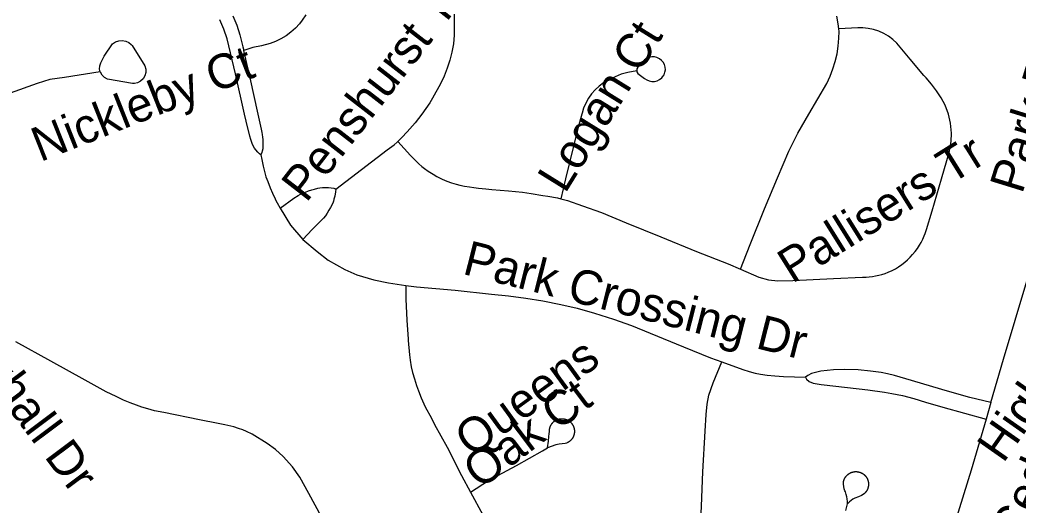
# Model space of a CAD drawing. Extents: x 1383679 to 1536984, y 460658 to 651027.
# Drawn here: x 1441302 to 1444051, y 495990 to 497325 of the extents above; entities that cross this region are included whole.
import ezdxf

# ---------------------------------------------------------------- set-up
doc = ezdxf.new("R2010")
doc.units = 0
doc.layers.add('Exist Road Non-System Type 51', color=7, linetype='Continuous')
doc.layers.add('Exist Road Non-System Type 51 Label', color=7, linetype='Continuous')

msp = doc.modelspace()

# ---------------------------------------------------------------- linework, layer by layer
at = {"layer": 'Exist Road Non-System Type 51'}
msp.add_line((1443976, 496272.3), (1443962.6, 496226.4), dxfattribs=at)
for points in [[(1443976, 496272.3), (1444010.6, 496391), (1444075, 496605.8), (1444091.2, 496671.9), (1444126.5, 496801.9), (1444159.9, 496915), (1444201.7, 497061.2), (1444203.1, 497066), (1444258.6, 497256.9), (1444298.8, 497399.9), (1444355.4, 497592.6), (1444400.6, 497747.6), (1444423.3, 497828.4), (1444445.6, 497913.6), (1444461.2, 497973.2), (1444493.5, 498085.3), (1444514.6, 498156.8)], [(1441888.4, 497336.8), (1441898.7, 497310.8), (1441907.5, 497284.3), (1441915.7, 497251.4), (1441918.1, 497241.2)], [(1442089.1, 497339.5), (1442079, 497324.4), (1442071.3, 497314.4), (1442060.2, 497302.3), (1442048, 497291.3), (1442034.8, 497281.6), (1442020.7, 497273.1), (1442005.9, 497266.1), (1441990.5, 497260.5), (1441966.9, 497254.1), (1441942.9, 497249.2), (1441940.1, 497248.7), (1441918.1, 497241.2)], [(1442497.6, 497341.2), (1442498, 497282.8), (1442495.5, 497259.7), (1442491.4, 497236.8), (1442485.7, 497214.3), (1442478.6, 497192.1), (1442470, 497170.5), (1442459.9, 497149.6), (1442438, 497109.7), (1442430.8, 497097.2), (1442408.6, 497066), (1442390.5, 497041.9), (1442368.6, 497017.3), (1442353.6, 497001.6), (1442342.5, 496990.3)], [(1443556.8, 497300.4), (1443555.2, 497314.5), (1443551.3, 497335.1)], [(1441965.1, 496953.3), (1441961.7, 496956.9), (1441956.9, 496961.5), (1441951.6, 496967.1), (1441947.9, 496971.9), (1441943.9, 496978.7), (1441941.4, 496985.1), (1441937.7, 496996.3), (1441935.3, 497005.4), (1441924.8, 497046.7), (1441920.4, 497066), (1441895.8, 497176.5), (1441872.1, 497273.5), (1441863.1, 497299.5), (1441852.6, 497325)], [(1443286.6, 496638.5), (1443336.6, 496617.3), (1443363.7, 496609.8), (1443388.9, 496607.2), (1443430.5, 496607.9), (1443542.3, 496613.3), (1443622.5, 496616.9), (1443624, 496617), (1443632.3, 496617.2), (1443640.2, 496617.7), (1443650.1, 496618.9), (1443658.2, 496620.3), (1443667.5, 496622.3), (1443675.3, 496624.4), (1443684.3, 496627.3), (1443693.1, 496630.7), (1443703.7, 496635.6), (1443712.8, 496640.3), (1443721.1, 496645.3), (1443730.2, 496651.5), (1443738.6, 496657.9), (1443746.4, 496664.7), (1443753.8, 496671.8), (1443760.4, 496678.9), (1443767.6, 496687.7), (1443773.5, 496695.9), (1443779.5, 496705.2), (1443783.8, 496712.8), (1443788.1, 496721.3), (1443792, 496730.4), (1443794.6, 496737.2), (1443798.1, 496748), (1443814.1, 496799.6), (1443840.3, 496888.1), (1443860.7, 496959.7), (1443866.5, 496990), (1443867.2, 497013.3), (1443864.8, 497040.8), (1443859, 497066), (1443850.1, 497090.2), (1443838.9, 497110.5), (1443826.3, 497130), (1443812.4, 497148.5), (1443797.3, 497166.1), (1443791.3, 497172.4), (1443754, 497216.9), (1443716.8, 497261.4), (1443705.7, 497271.5), (1443693.7, 497280.3), (1443680.8, 497287.8), (1443667.1, 497293.9), (1443652.9, 497298.6), (1443638.3, 497301.7), (1443623.4, 497303.3), (1443609, 497303.3), (1443556.8, 497300.4)], [(1443286.6, 496638.5), (1443294.2, 496660.4), (1443313.2, 496706.7), (1443352.6, 496805.1), (1443388.1, 496890.6), (1443419.3, 496963.6), (1443444.5, 497013.1), (1443474.5, 497066), (1443523.8, 497150.5), (1443533.1, 497170), (1443541, 497190.2), (1443547.4, 497210.8), (1443552.3, 497231.9), (1443555.6, 497253.2), (1443557.3, 497274.8), (1443557.6, 497293.6), (1443556.8, 497300.4)], [(1441523, 497182), (1441521.1, 497189.9), (1441521.7, 497199.1), (1441524.6, 497207.2), (1441525.7, 497209.1), (1441534.1, 497225), (1441556.4, 497258.9), (1441565.1, 497264.8), (1441574.1, 497268), (1441583.6, 497268.8), (1441593, 497267.1), (1441601.7, 497263.2), (1441608.5, 497257.6), (1441610.9, 497255), (1441645.5, 497198.4), (1441648.1, 497189.5), (1441648.2, 497180.1), (1441645.7, 497171), (1441640.9, 497162.9), (1441634.2, 497156.5), (1441625.9, 497152), (1441617.1, 497150.1), (1441611.4, 497150.1), (1441542.9, 497162.1), (1441534.6, 497166.4), (1441527.9, 497172.8), (1441523.3, 497180.9), (1441523, 497182)], [(1441965.1, 496953.3), (1441968.5, 496960), (1441970.1, 496965), (1441971.4, 496971.4), (1441971.8, 496977), (1441971.9, 496983.6), (1441971.8, 496990.4), (1441971.4, 496996.4), (1441971, 497002.8), (1441969.9, 497009.8), (1441968.8, 497014.9), (1441966.8, 497024.3), (1441957.9, 497066), (1441936, 497165.9), (1441918.1, 497241.2)], [(1443000.5, 497185.3), (1443001.2, 497182), (1443003.5, 497178.1), (1443007, 497175.3), (1443007.1, 497175.3), (1443021.9, 497164.1), (1443028.1, 497159.9), (1443035, 497157.1), (1443042.3, 497155.8), (1443049.7, 497156), (1443056.9, 497157.9), (1443063.6, 497161.2), (1443069.4, 497165.8), (1443071.6, 497168.2), (1443075.6, 497174.2), (1443078.2, 497180.9), (1443079.3, 497188), (1443078.9, 497195.2), (1443076.8, 497202.1), (1443073.4, 497208.4), (1443068.6, 497213.8), (1443068.6, 497213.8), (1443062.8, 497218.3), (1443056.1, 497221.5), (1443049, 497223.3), (1443041.6, 497223.5), (1443034.3, 497222.1), (1443027.5, 497219.2), (1443021.5, 497215), (1443019.9, 497213.4), (1443006.5, 497197.6), (1443003.2, 497194.7), (1443001, 497190.8), (1443000.3, 497186.3), (1443000.5, 497185.3)], [(1441523, 497182), (1441424.4, 497166.6), (1441383.8, 497160.8), (1441348.9, 497150.2), (1441275.1, 497123.9)], [(1443000.5, 497185.3), (1442975.5, 497180.4), (1442957.9, 497175.4), (1442940.9, 497168.9), (1442924.5, 497160.9), (1442908.8, 497151.5), (1442897.1, 497143.2), (1442886.1, 497132.9), (1442876.2, 497121.6), (1442867.5, 497109.3), (1442860.2, 497096.2), (1442854.3, 497082.4), (1442849.9, 497068), (1442849.4, 497066), (1442839.5, 497029.5), (1442804.2, 496888), (1442791.8, 496833)], [(1442171.3, 496859.6), (1442313.1, 496967.5), (1442332.1, 496981.4), (1442340.6, 496988.4), (1442342.5, 496990.3)], [(1442342.5, 496990.3), (1442377, 496951.8), (1442385.3, 496943.9), (1442392.9, 496936), (1442400.1, 496929.3), (1442408.6, 496921.5), (1442415.5, 496915.9), (1442426.1, 496908.8), (1442439.5, 496900.2), (1442449.9, 496894.1), (1442464.9, 496887.1), (1442477.5, 496881.6), (1442490.4, 496876.7), (1442502.7, 496872.8), (1442513.4, 496870.2), (1442525.9, 496867.5), (1442540.3, 496865.2), (1442551.7, 496863.8), (1442565.1, 496862), (1442585.2, 496860), (1442601.7, 496858.4), (1442647.7, 496854.3), (1442686.1, 496850.5), (1442710, 496847.1), (1442741.5, 496842.2), (1442755.7, 496839.5), (1442781.8, 496835.7), (1442791.8, 496833)], [(1441965.1, 496953.3), (1441967.5, 496940.6), (1441971.2, 496922.3), (1441975, 496907.5), (1441979.3, 496893.6), (1441984, 496880), (1441990.8, 496862.8), (1441997, 496848), (1442004.4, 496832.4), (1442004.9, 496831.3), (1442009.8, 496821.6), (1442018.2, 496806.6)], [(1442018.2, 496806.6), (1442056.1, 496834.3), (1442067.8, 496841.8), (1442074.3, 496845.3), (1442079.9, 496848.1), (1442087.9, 496851.4), (1442096.3, 496854.5), (1442105.2, 496857.3), (1442113.2, 496859.6), (1442122.4, 496861.7), (1442127.8, 496862.6), (1442135.3, 496863.4), (1442143.3, 496863.5), (1442151.6, 496863.4), (1442159.3, 496863), (1442166, 496862.1), (1442169, 496860.8), (1442171.3, 496859.6)], [(1442171.3, 496859.6), (1442170.6, 496851.6), (1442168.6, 496839.9), (1442166.6, 496831.3), (1442164.9, 496825.4), (1442164.9, 496825.4), (1442164.9, 496825.3), (1442164.9, 496825.3), (1442164.9, 496825.2), (1442164.8, 496825.2), (1442164.8, 496825.1), (1442164.8, 496825.1), (1442164.8, 496825), (1442164.8, 496825), (1442164.8, 496824.9), (1442164.8, 496824.9), (1442164.7, 496824.8), (1442164.7, 496824.8), (1442164.7, 496824.7), (1442164.7, 496824.7), (1442164.7, 496824.6), (1442164.7, 496824.6), (1442164.7, 496824.5), (1442164.6, 496824.5), (1442164.6, 496824.4), (1442164.6, 496824.4), (1442164.6, 496824.3), (1442164.6, 496824.3), (1442164.6, 496824.2), (1442164.6, 496824.2), (1442164.5, 496824.1), (1442164.5, 496824.1), (1442164.5, 496824), (1442164.5, 496824), (1442164.5, 496823.9), (1442164.5, 496823.9), (1442164.4, 496823.8), (1442164.4, 496823.8), (1442164.4, 496823.7), (1442164.4, 496823.7), (1442164.4, 496823.6), (1442164.4, 496823.6), (1442164.3, 496823.5), (1442164.3, 496823.5), (1442164.3, 496823.4), (1442164.3, 496823.4), (1442161.5, 496817), (1442157.1, 496808.7), (1442152.9, 496801.5), (1442147.9, 496793.5), (1442142.9, 496786.2), (1442137.7, 496779.3), (1442133.5, 496774.4), (1442123.5, 496764.7), (1442118.2, 496759.7), (1442107, 496748.2), (1442080.9, 496720.9)], [(1442018.2, 496806.6), (1442047.3, 496760.5), (1442080.9, 496720.9)], [(1442791.8, 496833), (1442810.2, 496827.9), (1442851.5, 496813.1), (1442903, 496794.8), (1442971.5, 496766.1), (1443066.8, 496728.4), (1443165.4, 496688), (1443252, 496653.3), (1443286.6, 496638.5)], [(1442080.9, 496720.9), (1442120.5, 496687.5), (1442150.5, 496664.1), (1442196.8, 496637.8), (1442229.9, 496623.8), (1442276.8, 496610), (1442316.5, 496601), (1442364.5, 496594.3)], [(1442364.5, 496594.3), (1442364.3, 496556.6), (1442367.5, 496498.9), (1442371.2, 496446.2), (1442371.4, 496442.9), (1442374.2, 496403.5), (1442376.5, 496388.1), (1442379.6, 496369.8), (1442383, 496354.3), (1442388, 496336.9), (1442393.8, 496318.6), (1442399.2, 496303.7), (1442406.7, 496285.1), (1442418.1, 496260.2), (1442434.8, 496228.3), (1442443.5, 496211.7), (1442478, 496148.8), (1442518.2, 496070.5), (1442542.7, 496025.3)], [(1442364.5, 496594.3), (1442394.2, 496590.2), (1442500.5, 496580.8), (1442600.3, 496570.4), (1442647.4, 496565.5), (1442695.2, 496558.8), (1442741.5, 496551.5), (1442791.2, 496541.4), (1442836.2, 496531.2), (1442884, 496517.4), (1442936.3, 496501.5), (1442986.3, 496484.1), (1443037.5, 496463.2), (1443129.3, 496425.3), (1443203.3, 496395.2), (1443234.6, 496384)], [(1442132.2, 495957), (1442097.7, 496021.6), (1442072.7, 496066.2), (1442052.3, 496094.6), (1442026.9, 496123), (1442005.8, 496142.2), (1441982.9, 496159.4), (1441941.4, 496184.4), (1441926, 496191.8), (1441915.2, 496196.5), (1441903.8, 496200.5), (1441891.2, 496204.6), (1441866.3, 496210.4), (1441847.6, 496214.5), (1441796, 496224.5), (1441698.2, 496243.9), (1441672.2, 496249.2), (1441654, 496254), (1441637.2, 496259.3), (1441622.5, 496264.1), (1441605.1, 496270.7), (1441586.5, 496278.7), (1441566.3, 496288.1), (1441538.8, 496301.4), (1441481.7, 496332.9), (1441386.9, 496385.9), (1441290.3, 496439.1)], [(1443095.4, 495761.7), (1443101.6, 495768), (1443111.5, 495779.3), (1443119.8, 495789.6), (1443128.6, 495802), (1443137.1, 495815.2), (1443148.1, 495834.6), (1443155, 495850.3), (1443161.6, 495868.4), (1443166.7, 495886.2), (1443171.6, 495907.9), (1443174.7, 495928.4), (1443176.9, 495948.2), (1443178.6, 495986.7), (1443182.9, 496081.4), (1443188.7, 496192.5), (1443191.5, 496238.4), (1443194.3, 496267), (1443199.3, 496292.4), (1443211.2, 496326.3), (1443234.6, 496384)], [(1443234.6, 496384), (1443293.1, 496362.9), (1443310, 496357), (1443327, 496353), (1443341.3, 496349.9), (1443359.6, 496346.7), (1443381.1, 496345.1), (1443405, 496343.3), (1443464.9, 496341.2)], [(1443976, 496272.3), (1443917.5, 496286), (1443856.4, 496303.4), (1443741.4, 496337.4), (1443710.1, 496346.4), (1443691.4, 496350.8), (1443674, 496354), (1443643.9, 496358.3), (1443609.9, 496361.8), (1443573.2, 496362.6), (1443542, 496361.6), (1443507.2, 496358.1), (1443482, 496351.9), (1443471.4, 496346), (1443464.9, 496341.2)], [(1443464.9, 496341.2), (1443467.7, 496335.7), (1443475.2, 496330), (1443486.7, 496325.4), (1443508.7, 496321.5), (1443581, 496313.3), (1443637.4, 496306.4), (1443683.3, 496300), (1443703.3, 496297), (1443732.8, 496291.1), (1443763.4, 496283), (1443795.9, 496273.1), (1443843.2, 496259.1), (1443962.6, 496226.4)], [(1442755, 496146.9), (1442757.9, 496165.2), (1442758.8, 496178), (1442759.5, 496186), (1442759.9, 496192.3), (1442760.6, 496198.2), (1442762.5, 496205.1), (1442765.2, 496211.6), (1442765.6, 496212.1), (1442765.9, 496212.6), (1442766.3, 496213.1), (1442766.6, 496213.6), (1442767, 496214), (1442767.4, 496214.5), (1442767.8, 496215), (1442768.2, 496215.4), (1442768.6, 496215.9), (1442769, 496216.3), (1442769.4, 496216.8), (1442769.8, 496217.2), (1442770.3, 496217.6), (1442770.7, 496218), (1442771.2, 496218.4), (1442771.6, 496218.8), (1442772.1, 496219.2), (1442772.6, 496219.6), (1442773, 496220), (1442773.5, 496220.3), (1442774, 496220.7), (1442774.5, 496221), (1442775, 496221.4), (1442775.5, 496221.7), (1442776, 496222), (1442776.5, 496222.3), (1442777.1, 496222.6), (1442777.6, 496222.9), (1442778.1, 496223.2), (1442778.6, 496223.5), (1442779.2, 496223.7), (1442779.7, 496224), (1442780.3, 496224.2), (1442780.8, 496224.5), (1442781.4, 496224.7), (1442782, 496224.9), (1442782.5, 496225.1), (1442783.1, 496225.3), (1442783.7, 496225.5), (1442784.3, 496225.7), (1442784.8, 496225.9), (1442785.4, 496226), (1442786, 496226.2), (1442786.6, 496226.3), (1442787.2, 496226.4), (1442787.8, 496226.6), (1442788.4, 496226.7), (1442789, 496226.8), (1442789.6, 496226.8), (1442790.2, 496226.9), (1442790.8, 496227), (1442791.4, 496227), (1442792, 496227.1), (1442792.6, 496227.1), (1442793.2, 496227.1), (1442793.8, 496227.2), (1442794.4, 496227.2), (1442795, 496227.1), (1442795.6, 496227.1), (1442796.2, 496227.1), (1442796.8, 496227.1), (1442797.4, 496227), (1442798, 496227), (1442798.6, 496226.9), (1442799.2, 496226.8), (1442799.8, 496226.7), (1442800.4, 496226.6), (1442801, 496226.5), (1442801.6, 496226.4), (1442802.2, 496226.2), (1442802.7, 496226.1), (1442803.3, 496225.9), (1442803.9, 496225.8), (1442804.5, 496225.6), (1442805.1, 496225.4), (1442805.6, 496225.2), (1442806.2, 496225), (1442806.8, 496224.8), (1442807.3, 496224.6), (1442807.9, 496224.4), (1442808.4, 496224.1), (1442809, 496223.9), (1442809.5, 496223.6), (1442810.1, 496223.3), (1442810.6, 496223), (1442811.1, 496222.8), (1442811.7, 496222.5), (1442812.2, 496222.2), (1442812.7, 496221.8), (1442813.2, 496221.5), (1442813.7, 496221.2), (1442814.2, 496220.8)], [(1442814.2, 496220.8), (1442814.7, 496220.5), (1442815.2, 496220.1), (1442815.7, 496219.8), (1442816.1, 496219.4), (1442816.6, 496219), (1442817, 496218.6), (1442817.5, 496218.2), (1442817.9, 496217.8), (1442818.4, 496217.4), (1442818.8, 496217), (1442819.2, 496216.5), (1442819.6, 496216.1), (1442820.1, 496215.6), (1442820.5, 496215.2), (1442820.8, 496214.7), (1442821.2, 496214.3), (1442821.6, 496213.8), (1442822, 496213.3), (1442822.3, 496212.8), (1442822.7, 496212.3), (1442823, 496211.8), (1442823.4, 496211.3), (1442823.7, 496210.8), (1442824, 496210.3), (1442824.3, 496209.8), (1442824.6, 496209.3), (1442824.9, 496208.7), (1442825.2, 496208.2), (1442825.4, 496207.7), (1442825.7, 496207.1), (1442825.9, 496206.6), (1442826.2, 496206), (1442826.4, 496205.4), (1442826.6, 496204.9), (1442826.9, 496204.3), (1442827.1, 496203.8), (1442827.2, 496203.2), (1442827.4, 496202.6), (1442827.6, 496202), (1442827.8, 496201.4), (1442827.9, 496200.9), (1442828.1, 496200.3), (1442828.2, 496199.7), (1442828.3, 496199.1), (1442828.4, 496198.5), (1442828.5, 496197.9), (1442828.6, 496197.3), (1442828.7, 496196.7), (1442828.8, 496196.1), (1442828.8, 496195.5), (1442828.9, 496194.9), (1442828.9, 496194.3), (1442828.9, 496193.7), (1442829, 496193.1), (1442829, 496192.5), (1442829, 496191.9), (1442828.9, 496191.3), (1442828.9, 496190.7), (1442828.9, 496190.1), (1442828.8, 496189.5), (1442828.8, 496188.9), (1442828.7, 496188.3), (1442828.6, 496187.7), (1442828.5, 496187.1), (1442828.5, 496186.5), (1442828.3, 496185.9), (1442828.2, 496185.3), (1442828.1, 496184.7), (1442828, 496184.1), (1442827.8, 496183.5), (1442827.6, 496183), (1442827.5, 496182.4), (1442827.3, 496181.8), (1442827.1, 496181.2), (1442826.9, 496180.7), (1442826.7, 496180.1), (1442826.5, 496179.5), (1442826.3, 496179), (1442826, 496178.4), (1442825.8, 496177.9), (1442825.5, 496177.3), (1442825.2, 496176.8), (1442825, 496176.2), (1442824.7, 496175.7), (1442824.4, 496175.2), (1442824.1, 496174.7), (1442823.8, 496174.1), (1442823.4, 496173.6), (1442823.1, 496173.1), (1442822.8, 496172.6), (1442822.4, 496172.1), (1442822.1, 496171.6), (1442821.7, 496171.2), (1442821.3, 496170.7), (1442821, 496170.2), (1442820.6, 496169.8), (1442820.2, 496169.3), (1442819.8, 496168.9), (1442819.3, 496168.4)], [(1443962.6, 496226.4), (1443921.6, 496085.9), (1443857.3, 495878.6), (1443827.4, 495829.6), (1443809.3, 495779.1), (1443791.8, 495725.1), (1443770.7, 495631.7), (1443765.8, 495601.3), (1443762, 495563.8), (1443762, 495536.9), (1443763.1, 495510.2), (1443766.5, 495476.5), (1443772.4, 495445.8), (1443799.8, 495338), (1443822.1, 495273.7)], [(1442542.7, 496025.3), (1442591.8, 496057.1), (1442669.4, 496098), (1442741.1, 496139), (1442755, 496146.9)], [(1442819.3, 496168.4), (1442818.9, 496168), (1442818.5, 496167.6), (1442818.1, 496167.1), (1442817.6, 496166.7), (1442817.2, 496166.3), (1442816.7, 496165.9), (1442816.3, 496165.5), (1442815.8, 496165.2), (1442815.3, 496164.8), (1442814.8, 496164.4), (1442814.3, 496164.1), (1442813.8, 496163.7), (1442813.3, 496163.4), (1442812.8, 496163.1), (1442812.3, 496162.8), (1442811.8, 496162.4), (1442811.3, 496162.1), (1442810.7, 496161.8), (1442810.2, 496161.6), (1442809.7, 496161.3), (1442809.1, 496161), (1442808.6, 496160.8), (1442808, 496160.5), (1442807.5, 496160.3), (1442803.1, 496159.1), (1442787, 496156.8), (1442777.6, 496154.9), (1442755, 496146.9)], [(1443580.6, 495992.5), (1443580.5, 495999.3), (1443579.7, 496006.8), (1443578.8, 496012.3), (1443577.2, 496018.9), (1443575.2, 496025.6), (1443574, 496028.4), (1443572, 496034.5), (1443570.6, 496040.3), (1443569.9, 496047.4), (1443570.2, 496054.4), (1443570.3, 496055), (1443570.5, 496055.6), (1443570.6, 496056.2), (1443570.8, 496056.8), (1443571, 496057.3), (1443571.2, 496057.9), (1443571.4, 496058.5), (1443571.6, 496059), (1443571.8, 496059.6), (1443572, 496060.2), (1443572.2, 496060.7), (1443572.5, 496061.3), (1443572.7, 496061.8), (1443573, 496062.4), (1443573.3, 496062.9), (1443573.6, 496063.4), (1443573.9, 496064), (1443574.2, 496064.5), (1443574.5, 496065), (1443574.8, 496065.5), (1443575.1, 496066), (1443575.5, 496066.5), (1443575.8, 496067), (1443576.2, 496067.5), (1443576.5, 496068), (1443576.9, 496068.5), (1443577.3, 496068.9), (1443577.7, 496069.4), (1443578.1, 496069.8), (1443578.5, 496070.3), (1443578.9, 496070.7), (1443579.3, 496071.2), (1443579.7, 496071.6), (1443580.2, 496072), (1443580.6, 496072.4), (1443581.1, 496072.8), (1443581.5, 496073.2), (1443582, 496073.6), (1443582.4, 496074), (1443582.9, 496074.4), (1443583.4, 496074.7), (1443583.9, 496075.1), (1443584.4, 496075.4), (1443584.9, 496075.8), (1443585.4, 496076.1), (1443585.9, 496076.4), (1443586.4, 496076.7), (1443586.9, 496077), (1443587.5, 496077.3), (1443588, 496077.6), (1443588.5, 496077.9), (1443589.1, 496078.2), (1443589.6, 496078.4), (1443590.2, 496078.7), (1443590.7, 496078.9), (1443591.3, 496079.1), (1443591.8, 496079.3), (1443592.4, 496079.5), (1443593, 496079.7), (1443593.6, 496079.9), (1443594.1, 496080.1), (1443594.7, 496080.3), (1443595.3, 496080.4), (1443595.9, 496080.6), (1443596.5, 496080.7), (1443597.1, 496080.9), (1443597.7, 496081), (1443598.2, 496081.1), (1443598.8, 496081.2), (1443599.4, 496081.3), (1443600, 496081.3), (1443600.6, 496081.4), (1443601.2, 496081.5), (1443601.8, 496081.5), (1443602.4, 496081.5), (1443603.1, 496081.6), (1443603.7, 496081.6), (1443604.3, 496081.6), (1443604.9, 496081.6), (1443605.5, 496081.5), (1443606.1, 496081.5), (1443606.7, 496081.5), (1443607.3, 496081.4), (1443607.9, 496081.4), (1443608.5, 496081.3), (1443609.1, 496081.2), (1443609.7, 496081.1), (1443610.3, 496081), (1443610.9, 496080.9)], [(1443610.9, 496080.9), (1443611.4, 496080.8), (1443612, 496080.6), (1443612.6, 496080.5), (1443613.2, 496080.4), (1443613.8, 496080.2), (1443614.4, 496080), (1443614.9, 496079.8), (1443615.5, 496079.6), (1443616.1, 496079.4), (1443616.6, 496079.2), (1443617.2, 496079), (1443617.8, 496078.8), (1443618.3, 496078.5), (1443618.9, 496078.3), (1443619.4, 496078), (1443619.9, 496077.7), (1443620.5, 496077.5), (1443621, 496077.2), (1443621.5, 496076.9), (1443622.1, 496076.6), (1443622.6, 496076.2), (1443623.1, 496075.9), (1443623.6, 496075.6), (1443624.1, 496075.2), (1443624.6, 496074.9), (1443625.1, 496074.5), (1443625.5, 496074.2), (1443626, 496073.8), (1443626.5, 496073.4), (1443626.9, 496073), (1443627.4, 496072.6), (1443627.8, 496072.2), (1443628.3, 496071.8), (1443628.7, 496071.4), (1443629.1, 496070.9), (1443629.5, 496070.5), (1443629.9, 496070), (1443630.3, 496069.6), (1443630.7, 496069.1), (1443631.1, 496068.7), (1443631.5, 496068.2), (1443631.9, 496067.7), (1443632.2, 496067.2), (1443632.6, 496066.7), (1443632.9, 496066.2), (1443633.2, 496065.7), (1443633.6, 496065.2), (1443633.9, 496064.7), (1443634.2, 496064.2), (1443634.5, 496063.7), (1443634.8, 496063.1), (1443635, 496062.6), (1443635.3, 496062.1), (1443635.6, 496061.5), (1443635.8, 496061), (1443636.1, 496060.4), (1443636.3, 496059.9), (1443636.5, 496059.3), (1443636.7, 496058.7), (1443636.9, 496058.2), (1443637.1, 496057.6), (1443637.3, 496057), (1443637.5, 496056.4), (1443637.6, 496055.9), (1443637.8, 496055.3), (1443637.9, 496054.7), (1443638.1, 496054.1), (1443638.2, 496053.5), (1443638.3, 496052.9), (1443638.4, 496052.3), (1443638.5, 496051.7), (1443638.6, 496051.1), (1443638.6, 496050.5), (1443638.7, 496049.9), (1443638.7, 496049.3), (1443638.8, 496048.7), (1443638.8, 496048.1), (1443638.8, 496047.5), (1443638.8, 496046.9), (1443638.8, 496046.3), (1443638.8, 496045.7), (1443638.8, 496045.1), (1443638.8, 496044.5), (1443638.7, 496043.9), (1443638.7, 496043.3), (1443638.6, 496042.7), (1443638.5, 496042.1), (1443638.4, 496041.5), (1443638.3, 496040.9), (1443638.2, 496040.3), (1443638.1, 496039.7), (1443638, 496039.1), (1443637.8, 496038.5), (1443637.7, 496037.9), (1443637.5, 496037.4), (1443637.4, 496036.8), (1443637.2, 496036.2), (1443637, 496035.6), (1443636.8, 496035.1)], [(1442542.7, 496025.3), (1442576.6, 495962.4), (1442620.6, 495879.6)], [(1443636.8, 496035.1), (1443636.6, 496034.5), (1443636.4, 496033.9), (1443636.1, 496033.4), (1443635.9, 496032.8), (1443635.6, 496032.3), (1443635.4, 496031.7), (1443635.1, 496031.2), (1443634.8, 496030.6), (1443634.6, 496030.1), (1443634.3, 496029.6), (1443634, 496029.1), (1443633.6, 496028.5), (1443633.3, 496028), (1443633, 496027.5), (1443632.7, 496027), (1443632.3, 496026.5), (1443632, 496026.1), (1443631.6, 496025.6), (1443631.2, 496025.1), (1443630.8, 496024.6), (1443630.4, 496024.2), (1443630, 496023.7), (1443629.6, 496023.3), (1443629.2, 496022.8), (1443628.8, 496022.4), (1443628.4, 496022), (1443627.9, 496021.5), (1443624.2, 496018.9), (1443619.3, 496015.9), (1443611.1, 496012.5), (1443610.8, 496012.4), (1443600.8, 496008.3), (1443595.9, 496005.3), (1443591.5, 496002.4), (1443586.7, 495998.7), (1443580.6, 495992.5)], [(1443576.1, 495974.8), (1443580.6, 495992.5)]]:
    msp.add_lwpolyline(points, dxfattribs=at)

# ---------------------------------------------------------------- texts
at = {"layer": 'Exist Road Non-System Type 51 Label'}
for s, rotation, p in [('Penshurst Trace', 52.2125, (1442090.4, 496819.7)), ('Logan Ct', 58.208, (1442803.2, 496844.8)), ('Park Rd', 72.8493, (1444062, 496843.7)), ('Nickleby Ct', 21.6005, (1441357.7, 496933.4)), ('High Hamptons Dr', 54.9799, (1444010, 496102.4)), ('Pallisers Tr', 32.0062, (1443428.4, 496597.9)), ('Park Crossing Dr', 345.7978, (1442517.7, 496626.6)), ('Foxhall Dr', 306.7878, (1441100.4, 496479.7)), ('Queens', 35.9467, (1442544.8, 496118.4)), ('Sweet Cedar Ln', 65.9071, (1443899.3, 495524.7)), ('Oak Ct', 36.9717, (1442569, 496030.8))]:
    msp.add_text(s, height=95, rotation=rotation, dxfattribs=at).set_placement(p)

doc.saveas('drawing.dxf')
